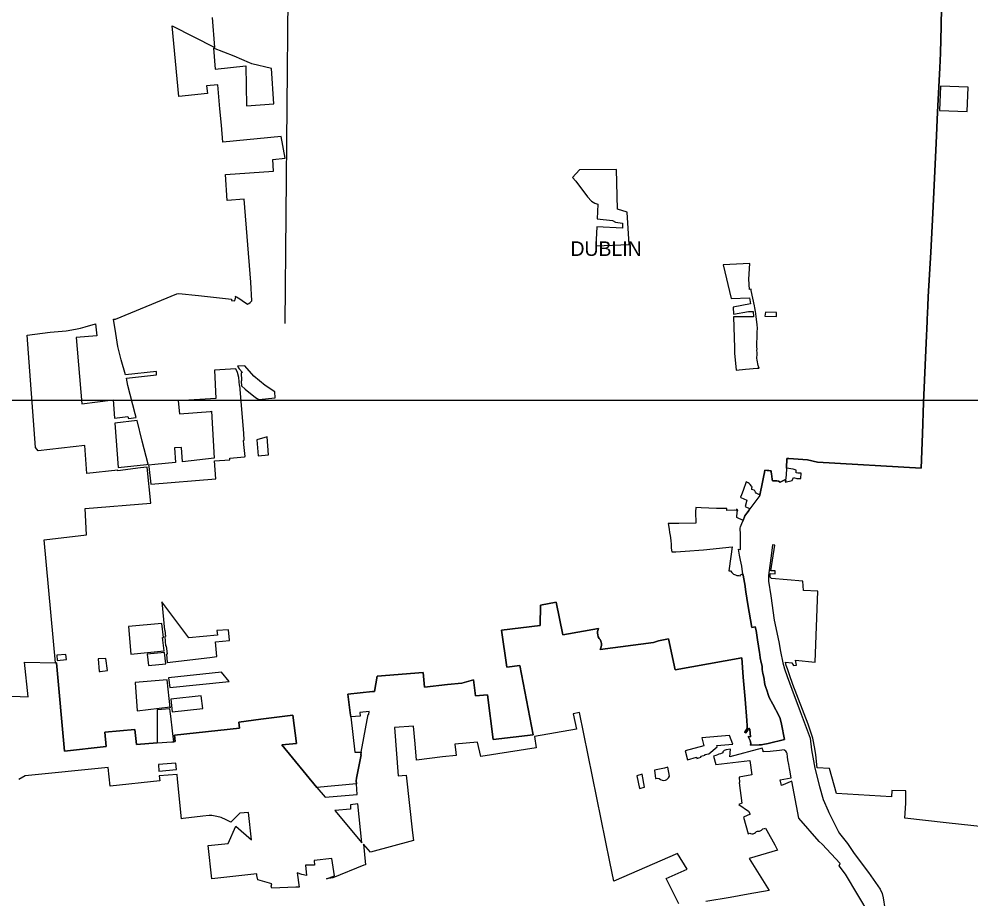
# Model space of a CAD drawing. Extents: x 1597222 to 1925846, y 496284 to 911751.
# Drawn here: x 1771869 to 1804633, y 748344 to 778623 of the extents above; entities that cross this region are included whole.
import ezdxf

# ---------------------------------------------------------------- set-up
doc = ezdxf.new("R2010")
doc.units = 0
for name, color, linetype in [('GM_X_Adjacent_County', 7, 'Continuous'), ('GM_X_Corporation', 7, 'Continuous'), ('GM_X_Corporation_Text', 7, 'Continuous'), ('SC_Scratch1', 7, 'Continuous')]:
    doc.layers.add(name, color=color, linetype=linetype)

msp = doc.modelspace()

# ---------------------------------------------------------------- linework, layer by layer
at = {"layer": 'GM_X_Adjacent_County'}
msp.add_line((1781136, 781321), (1781021, 768152), dxfattribs=at)
at = {"layer": 'GM_X_Corporation'}
for points in [[(1770221, 755380), (1772181, 755302), (1772057, 756492), (1773124, 756470), (1773153, 756469), (1773437, 753432), (1774866, 753591), (1774825, 754079), (1775856, 754180), (1775906, 753660), (1776624, 753722), (1777130, 753751), (1777182, 753756), (1777187, 753756), (1777192, 753756), (1777203, 753757), (1777227, 753759), (1777248, 753761), (1777222, 753980), (1779459, 754220), (1779429, 754427), (1780187, 754529), (1781295, 754669), (1781415, 753697), (1780909, 753642), (1782119, 752179), (1782408, 751849), (1783508, 751942), (1783479, 752309), (1783471, 752408), (1783484, 752497), (1783649, 753302), (1783633, 753301), (1783649, 753390), (1783882, 754688), (1783903, 754693), (1783921, 754795), (1783593, 754757), (1783615, 754639), (1783284, 754607), (1783265, 754751), (1783184, 755392), (1784040, 755478), (1784107, 755485), (1784200, 756011), (1785774, 756133), (1785821, 755634), (1786620, 755722), (1787106, 755772), (1787508, 755887), (1787585, 755334), (1787998, 755364), (1788193, 753835), (1789563, 753993), (1789108, 756382), (1788659, 756318), (1788479, 757590), (1789807, 757755), (1789818, 758450), (1790355, 758555), (1790586, 757428), (1791817, 757651), (1791798, 757614), (1791788, 757587), (1791780, 757546), (1791782, 757487), (1791788, 757438), (1791805, 757364), (1791835, 757312), (1791867, 757269), (1791892, 757218), (1791908, 757179), (1791915, 757135), (1791911, 757075), (1791904, 757024), (1791892, 756983), (1791876, 756928), (1793703, 757167), (1793873, 757222), (1794220, 757291), (1794455, 756226), (1796742, 756644), (1796798, 755979), (1796859, 755222), (1796915, 754482), (1796927, 754304), (1796931, 754250), (1796929, 754213), (1796912, 754181), (1796877, 754133), (1796843, 754097), (1796883, 754064), (1796952, 754150), (1796983, 754223), (1797022, 754175), (1797047, 753919), (1796968, 753934), (1797035, 753796), (1797053, 753693), (1797049, 753638), (1797341, 753647), (1797421, 753653), (1797474, 753661), (1797655, 753696), (1798210, 753829), (1798116, 754362), (1798071, 754553), (1798026, 754636), (1797814, 755043), (1797693, 755276), (1797657, 755384), (1797616, 755493), (1797564, 755654), (1797534, 755727), (1797500, 755975), (1797475, 756104), (1797452, 756237), (1797445, 756358), (1797413, 756483), (1797382, 756639), (1797361, 756753), (1797349, 756823), (1797285, 757257), (1797242, 757581), (1797210, 757710), (1797087, 757691), (1796955, 758481), (1796885, 758915), (1796847, 759179), (1796806, 759422), (1796792, 759498), (1796775, 759605), (1796742, 759796), (1796699, 760004), (1796671, 760173), (1796631, 760376), (1796701, 760373), (1796705, 760456), (1796703, 760557), (1796705, 760694), (1796699, 760891), (1796690, 761106), (1796705, 761148), (1796741, 761269), (1796792, 761362), (1796847, 761530), (1796917, 761623), (1796961, 761681), (1797003, 761733), (1797028, 761773), (1797374, 762223), (1797363, 762240), (1797453, 762684), (1797500, 762912), (1797522, 763017), (1797533, 763101), (1797623, 763091), (1797676, 763083), (1797721, 763081), (1797757, 763077), (1797761, 763030), (1797770, 762968), (1797782, 762885), (1797788, 762787), (1797797, 762730), (1797881, 762730), (1797948, 762730), (1798010, 762716), (1798071, 762682), (1798232, 762768), (1798251, 762763), (1798259, 762760), (1798240, 762681), (1798478, 762748), (1798523, 762842), (1798636, 762814), (1798776, 762808), (1798789, 762992), (1798672, 762998), (1798612, 763008), (1798618, 763105), (1798514, 763138), (1798285, 763163), (1798291, 763505), (1798362, 763501), (1799001, 763458), (1799354, 763375), (1802922, 763165), (1802964, 764353), (1803002, 765433), (1803091, 767476), (1803123, 768218), (1803140, 768585), (1803149, 768674), (1803153, 768757), (1803163, 769065), (1803249, 770602), (1803319, 771942), (1803430, 774349), (1803483, 775420), (1803558, 776945), (1803585, 777445), (1803603, 778383), (1803634, 779704)], [(1803634, 779704), (1803603, 778383), (1803585, 777445), (1803558, 776945), (1803483, 775420), (1803430, 774349), (1803319, 771942), (1803249, 770602), (1803163, 769065), (1803153, 768757), (1803149, 768674), (1803140, 768585), (1803123, 768218), (1803091, 767476), (1803002, 765433), (1802964, 764353), (1802922, 763165), (1799354, 763375), (1799001, 763458), (1798362, 763501), (1798291, 763505), (1798285, 763163), (1798285, 763121), (1798261, 762817), (1798251, 762763), (1798232, 762768), (1798071, 762682), (1798010, 762716), (1797948, 762730), (1797881, 762730), (1797797, 762730), (1797788, 762787), (1797782, 762885), (1797770, 762968), (1797761, 763030), (1797757, 763077), (1797721, 763081), (1797676, 763083), (1797623, 763091), (1797533, 763101), (1797522, 763017), (1797500, 762912), (1797453, 762684), (1797363, 762240), (1797328, 762261), (1797285, 762286), (1797235, 762306), (1797215, 762337), (1797189, 762393), (1797166, 762407), (1797095, 762431), (1797095, 762464), (1797096, 762492), (1797098, 762526), (1797079, 762553), (1797035, 762603), (1796999, 762638), (1796960, 762661), (1796901, 762700), (1796787, 762397), (1796734, 762256), (1796695, 762167), (1796714, 762158), (1796917, 762062), (1796864, 761847), (1797028, 761773), (1797003, 761733), (1796961, 761681), (1796917, 761623), (1796847, 761530), (1796792, 761362), (1796570, 761475), (1796586, 761667), (1796609, 761738), (1796566, 761754), (1796559, 761715), (1796509, 761719), (1796236, 761708), (1796228, 761782), (1795879, 761782), (1795343, 761802), (1795167, 761813), (1795148, 761662), (1795159, 761273), (1794583, 761261), (1794207, 761261), (1794244, 761065), (1794262, 760959), (1794275, 760853), (1794298, 760683), (1794310, 760545), (1794319, 760417), (1794336, 760293), (1794473, 760293), (1794798, 760307), (1795429, 760358), (1796412, 760460), (1796307, 759710), (1796302, 759633), (1796357, 759638), (1796408, 759574), (1796455, 759524), (1796534, 759493), (1796552, 759487), (1796578, 759477), (1796599, 759476), (1796640, 759471), (1796685, 759467), (1796706, 759495), (1796737, 759516), (1796763, 759510), (1796792, 759498), (1796806, 759422), (1796847, 759179), (1796885, 758915), (1796955, 758481), (1797087, 757691), (1797210, 757710), (1797242, 757581), (1797285, 757257), (1797349, 756823), (1797361, 756753), (1797382, 756639), (1797413, 756483), (1797445, 756358), (1797452, 756237), (1797475, 756104), (1797500, 755975), (1797534, 755727), (1797564, 755654), (1797616, 755493), (1797657, 755384), (1797693, 755276), (1797814, 755043), (1798026, 754636), (1798071, 754553), (1798116, 754362), (1798210, 753829), (1797655, 753696), (1797474, 753661), (1797421, 753653), (1797341, 753647), (1797049, 753638), (1797053, 753693), (1797035, 753796), (1796968, 753934), (1797047, 753919), (1797022, 754175), (1796983, 754223), (1796952, 754150), (1796883, 754064), (1796843, 754097), (1796877, 754133), (1796912, 754181), (1796929, 754213), (1796931, 754250), (1796927, 754304), (1796915, 754482), (1796859, 755222), (1796798, 755979), (1796742, 756644), (1794455, 756226), (1794220, 757291), (1793873, 757222), (1793703, 757167), (1791876, 756928), (1791892, 756983), (1791904, 757024), (1791911, 757075), (1791915, 757135), (1791908, 757179), (1791892, 757218), (1791867, 757269), (1791835, 757312), (1791805, 757364), (1791788, 757438), (1791782, 757487), (1791780, 757546), (1791788, 757587), (1791798, 757614), (1791817, 757651), (1790586, 757428), (1790355, 758555), (1789818, 758450), (1789807, 757755), (1788479, 757590), (1788659, 756318), (1789108, 756382), (1789563, 753993), (1788193, 753835), (1787998, 755364), (1787585, 755334), (1787508, 755887), (1787106, 755772), (1786620, 755722), (1785821, 755634), (1785774, 756133), (1784200, 756011), (1784107, 755485), (1784040, 755478), (1783184, 755392), (1783265, 754751), (1783284, 754607), (1783421, 753391), (1783649, 753390), (1783633, 753301), (1783649, 753302), (1783484, 752497), (1783471, 752408), (1783479, 752309), (1782119, 752179), (1780909, 753642), (1781415, 753697), (1781295, 754669), (1780187, 754529), (1779429, 754427), (1779459, 754220), (1777222, 753980), (1777248, 753761), (1777227, 753759), (1777203, 753757), (1777192, 753756), (1777150, 754125), (1777091, 754630), (1777072, 754794), (1777061, 754886), (1776626, 754848), (1776624, 753722), (1775906, 753660), (1775856, 754180), (1774825, 754079), (1774866, 753591), (1773437, 753432), (1773153, 756469), (1773124, 756470), (1772730, 760702), (1774189, 760869), (1774141, 761779), (1776402, 761968), (1776281, 763207), (1776046, 763174), (1775267, 763080), (1775267, 763099), (1774207, 762980), (1774134, 763952), (1772529, 763765), (1772435, 763880), (1772154, 767744), (1772941, 767852), (1773496, 767895), (1773812, 767946), (1773981, 767984), (1774140, 768026), (1774502, 768137), (1774541, 767725), (1773835, 767662), (1774031, 765380), (1775103, 765517), (1775155, 764887), (1775613, 764948), (1775632, 764875), (1775901, 764913), (1775868, 765038), (1775612, 766018), (1775562, 766261), (1776602, 766385), (1776595, 766499), (1775530, 766385), (1775389, 766892), (1775267, 767351), (1775201, 767808), (1775125, 768301), (1775186, 768299), (1777296, 769167), (1777365, 769179), (1778041, 769112), (1779178, 768980), (1779186, 768933), (1779291, 768930), (1779312, 768982), (1779321, 769021), (1779329, 769061), (1779309, 769075), (1779349, 769065), (1779409, 769034), (1779471, 768997), (1779544, 768942), (1779731, 768815), (1779777, 768829), (1779819, 768873), (1779857, 768907), (1779885, 768930), (1779843, 769567), (1779616, 772429), (1779035, 772377), (1778973, 773273), (1780624, 773390), (1780602, 773789), (1781025, 773834), (1780894, 774583), (1778880, 774385), (1778835, 774970), (1778780, 775529), (1778712, 776354), (1778326, 776325), (1778354, 776062), (1777374, 775955), (1777143, 778385), (1778610, 777639), (1778533, 778680)], [(1805153, 750816), (1803782, 750969), (1802362, 751127), (1802386, 751643), (1802395, 752068), (1801904, 752081), (1801902, 751864), (1800004, 751976), (1799768, 752839), (1799337, 752860), (1799288, 753301), (1799259, 753517), (1799195, 753873), (1799030, 754356), (1798507, 755721), (1798384, 756061), (1798314, 756259), (1798276, 756372), (1798244, 756489), (1798467, 756467), (1798529, 756374), (1798628, 756388), (1798591, 756564), (1799270, 756493), (1799367, 758939), (1798870, 758963), (1798849, 759277), (1797769, 759368), (1797722, 759416), (1797725, 759540), (1797893, 759534), (1797896, 759634), (1797741, 759640), (1797877, 760524), (1797803, 760530), (1797766, 760246), (1797665, 759477), (1797660, 759284), (1797739, 758775), (1797865, 757935), (1798015, 757195), (1798077, 756860), (1798161, 756466), (1798219, 756258), (1798311, 755995), (1798463, 755566), (1798749, 754795), (1798922, 754336), (1799095, 753877), (1799143, 753477), (1799257, 752840), (1799415, 752215), (1799549, 751765), (1799716, 751380), (1799745, 751315), (1800064, 750675), (1800110, 750597), (1800378, 750247), (1800618, 749910), (1801104, 749259), (1801506, 748678), (1801573, 748527), (1801614, 748387), (1801674, 748018)], [(1794574, 748180), (1794147, 749043), (1794865, 749373), (1794531, 749912), (1792336, 748961), (1792198, 749626), (1791164, 754755), (1790938, 754719), (1791056, 754185), (1789610, 753934), (1789671, 753539), (1787760, 753249), (1787654, 753742), (1786874, 753665), (1786906, 753382), (1786916, 753283), (1786443, 753233), (1785553, 753125), (1785499, 753683), (1785442, 754285), (1784796, 754242), (1784920, 752578), (1785195, 752599), (1785416, 750625), (1785444, 750360), (1783963, 749959), (1783729, 750233), (1783799, 749524), (1783741, 749503), (1782666, 749072), (1782456, 749036), (1782732, 749144), (1782633, 749738), (1782024, 749670), (1782040, 749512), (1781732, 749512), (1781763, 749148), (1781598, 749189), (1781445, 749241), (1781509, 748753), (1781398, 748749), (1780567, 748710), (1780546, 748779), (1780565, 748866), (1780090, 749006), (1780055, 749146), (1780051, 749207), (1778506, 749039), (1778382, 750183), (1779068, 750252), (1779327, 750854), (1779872, 750383), (1779761, 751324), (1779466, 751295), (1779153, 750981), (1778998, 751072), (1778827, 751143), (1778680, 751179), (1778562, 751205), (1778501, 751220), (1778415, 751215), (1778192, 751189), (1777521, 751114), (1777461, 751105), (1777328, 752466), (1777311, 752624), (1776693, 752582), (1776711, 752414), (1775007, 752225), (1774938, 752864), (1772077, 752586), (1771864, 752450)], [(1801161, 747779), (1800318, 749198), (1800097, 749485), (1800128, 749567), (1799507, 750229), (1799412, 750316), (1798706, 751120), (1798462, 752398), (1798117, 752249), (1798068, 752442), (1798442, 752517), (1798433, 752573), (1798413, 752720), (1798384, 752837), (1798362, 752976), (1798333, 753132), (1798318, 753240), (1798305, 753344), (1798285, 753395), (1798262, 753427), (1798227, 753454), (1798198, 753471), (1798041, 753453), (1797723, 753424), (1797479, 753412), (1797476, 753439), (1797450, 753537), (1796330, 753237), (1796353, 753497), (1796210, 753481), (1796143, 753449), (1796092, 753406), (1796093, 753377), (1796014, 753336), (1795954, 753326), (1795913, 753303), (1795847, 753280), (1795773, 753260), (1795848, 752973), (1797026, 753110), (1797087, 752615), (1796652, 752533), (1796671, 752350), (1796658, 752339), (1796746, 751636), (1796638, 751592), (1796977, 751366), (1797033, 751257), (1796799, 751155), (1796966, 750588), (1797025, 750609), (1797047, 750598), (1797092, 750589), (1797136, 750587), (1797160, 750598), (1797188, 750613), (1797217, 750636), (1797237, 750657), (1797253, 750666), (1797285, 750676), (1797298, 750681), (1797320, 750675), (1797341, 750673), (1797359, 750677), (1797381, 750690), (1797421, 750713), (1797454, 750740), (1797471, 750760), (1797531, 750772), (1797564, 750776), (1797603, 750700), (1797878, 750206), (1797975, 750025), (1796995, 749737), (1797690, 748639), (1796961, 748506), (1796340, 748394), (1795502, 748255)]]:
    msp.add_lwpolyline(points, dxfattribs=at)
for points in [[(1778615, 776896), (1779670, 777013), (1779697, 775634), (1780643, 775701), (1780556, 776916), (1779886, 777084), (1779855, 777098), (1779803, 777112), (1779802, 777121), (1779268, 777344), (1778560, 777617)], [(1803545, 775480), (1804498, 775441), (1804533, 776279), (1803582, 776318)], [(1791769, 771744), (1792292, 771693), (1792400, 771637), (1792636, 771596), (1792636, 771425), (1791754, 771473), (1791720, 770818), (1792869, 770863), (1792799, 771981), (1792464, 772084), (1792432, 773446), (1791163, 773438), (1790923, 773175), (1791037, 773050), (1791431, 772506), (1791571, 772357), (1791625, 772322), (1791688, 772291), (1791795, 772249)], [(1796099, 770163), (1796374, 769005), (1797006, 769026), (1797045, 768825), (1796452, 768712), (1796465, 768470), (1796979, 768555), (1797142, 768559), (1797150, 768374), (1796465, 768373), (1796499, 767312), (1796490, 767130), (1796555, 766544), (1796870, 766570), (1797279, 766609), (1797338, 766615), (1797312, 766701), (1797277, 766882), (1797259, 766955), (1797271, 767095), (1797270, 767147), (1797268, 767221), (1797269, 767275), (1797264, 767337), (1797264, 767536), (1797272, 767608), (1797272, 767726), (1797279, 767856), (1797281, 767972), (1797274, 768111), (1797235, 768372), (1797225, 768494), (1797217, 768565), (1797195, 768683), (1797178, 768750), (1797069, 769278), (1797065, 769330), (1797015, 769322), (1796989, 769674), (1797017, 770212)], [(1797541, 768401), (1797935, 768382), (1797940, 768524), (1797562, 768542)], [(1779526, 765996), (1779649, 765886), (1780007, 765600), (1780127, 765528), (1780688, 765588), (1780677, 765797), (1780336, 766018), (1779945, 766331), (1779640, 766689), (1779392, 766675), (1779449, 766592), (1779558, 766458), (1779517, 766446), (1779531, 766180), (1779519, 766152)], [(1777350, 765480), (1777390, 765033), (1778456, 765121), (1778497, 765124), (1778588, 763518), (1777500, 763383), (1777464, 763881), (1777215, 763863), (1777251, 763358), (1776548, 763289), (1776325, 763267), (1776334, 763222), (1776405, 762617), (1778638, 762800), (1778601, 763421), (1779128, 763459), (1779121, 763518), (1779630, 763563), (1779650, 763567), (1779608, 763988), (1779595, 764118), (1779623, 764127), (1779603, 764375), (1779472, 766012), (1779452, 766010), (1779430, 766292), (1779392, 766458), (1779331, 766585), (1778592, 766543), (1778640, 765564)], [(1775930, 764813), (1775164, 764721), (1775275, 763188), (1776254, 763296), (1776316, 763302), (1776105, 764098)], [(1780404, 764245), (1780055, 764138), (1780095, 763598), (1780455, 763628)], [(1776781, 758571), (1776874, 757598), (1776884, 757599), (1776909, 757379), (1776884, 757376), (1776915, 757049), (1776937, 757054), (1776962, 756765), (1776941, 756764), (1776966, 756480), (1778434, 756650), (1778682, 756690), (1778628, 757192), (1779114, 757236), (1779113, 757254), (1779078, 757609), (1778681, 757577), (1778697, 757425), (1777708, 757333)], [(1775632, 757715), (1775719, 756770), (1776867, 756883), (1776810, 757337), (1776839, 757343), (1776787, 757819)], [(1773167, 756733), (1773180, 756550), (1773499, 756580), (1773477, 756755)], [(1774587, 756604), (1774629, 756166), (1774663, 756170), (1774909, 756203), (1774860, 756623)], [(1776879, 756830), (1776278, 756765), (1776322, 756377), (1776922, 756430)], [(1776970, 755885), (1775862, 755797), (1775938, 754823), (1777065, 754950), (1777068, 754919)], [(1779096, 755830), (1778843, 756143), (1777018, 755954), (1777056, 755620)], [(1777098, 755224), (1777144, 754785), (1778199, 754896), (1778137, 755331)], [(1794796, 753442), (1794876, 753131), (1795181, 753219), (1795192, 753180), (1795272, 753203), (1795346, 753220), (1795335, 753259), (1795480, 753291), (1795474, 753312), (1795544, 753328), (1795606, 753339), (1795899, 753577), (1795891, 753624), (1796434, 753669), (1796318, 753969), (1795366, 753888), (1795438, 753609)], [(1776671, 752975), (1776681, 752746), (1777291, 752794), (1777271, 753017)], [(1793137, 752583), (1793226, 752140), (1793393, 752195), (1793317, 752638)], [(1793745, 752771), (1793775, 752489), (1793787, 752492), (1793842, 752499), (1793897, 752486), (1793951, 752453), (1794009, 752431), (1794065, 752420), (1794115, 752433), (1794167, 752458), (1794222, 752514), (1794260, 752570), (1794199, 752878), (1794082, 752848)], [(1783531, 751616), (1783273, 751584), (1783278, 751434), (1782734, 751391), (1783671, 750271)]]:
    msp.add_lwpolyline(points, close=True, dxfattribs=at)
at = {"layer": 'SC_Scratch1'}
msp.add_lwpolyline([(1729596, 899996), (1925846, 899996), (1925846, 765496), (1729596, 765496)], close=True, dxfattribs=at)

# ---------------------------------------------------------------- texts
at = {"layer": 'GM_X_Corporation_Text'}
msp.add_text('DUBLIN', height=500, rotation=0, dxfattribs=at).set_placement((1790848, 770472))

doc.saveas('drawing.dxf')
